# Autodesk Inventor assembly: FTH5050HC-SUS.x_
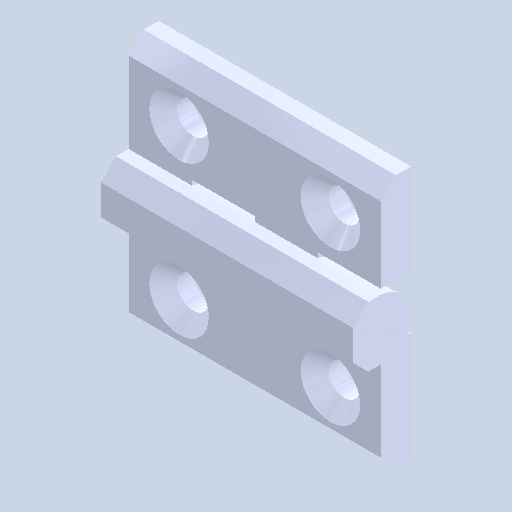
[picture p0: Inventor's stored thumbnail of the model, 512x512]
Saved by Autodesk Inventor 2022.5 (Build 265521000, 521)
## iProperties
Created: 2024-08
Part Number: FTH5050HC-SUS.x_
Document SubType Name: Assembly
Designer: ImaoCorp
Author: ImaoCorp
Sending System: SOLIDWORKS 2022-2022290
MC: AMD64
MC_MODEL: Intel64 Family 6 Model 60 Stepping 3, GenuineIntel
OS: Windows_NT
FRU: Parasolid Version 33.1, build 260,  4-25-2022
FORMAT: text
GUISE: transmit
KEY: FILEFTH5050HC-SUS.x_t
DATE: Mon Aug  5 14:46:37 2024
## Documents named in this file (4)
- Y:\5.更新分\2024年対応\0805_FTH\fth5050hc-sus\FTH5050HC-SUS.x_.iam
- Y:\5.更新分\2024年対応\0805_FTH\fth5050hc-sus\FTH5050HC-SUS_01.ipt
- Y:\5.更新分\2024年対応\0805_FTH\fth5050hc-sus\FTH5050HC-SUS_02.ipt
- Y:\5.更新分\2024年対応\0805_FTH\fth5050hc-sus\FTH5050HC-SUS_03.ipt
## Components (3 placed, 3 different names)
1. FTH5050HC-SUS_01
2. FTH5050HC-SUS_02
3. FTH5050HC-SUS_03
